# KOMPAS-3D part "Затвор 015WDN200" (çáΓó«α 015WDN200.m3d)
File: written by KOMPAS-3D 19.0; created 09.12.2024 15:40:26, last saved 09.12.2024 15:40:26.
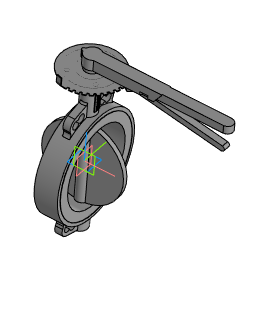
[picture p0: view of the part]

Document properties: Автор: Евгений; Полное имя файла: ..\Затвор 015WDN200.a3d

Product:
- Part/product: Затвор 015WDN200
    Масса: 21.8264

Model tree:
1. Операция без истории:1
